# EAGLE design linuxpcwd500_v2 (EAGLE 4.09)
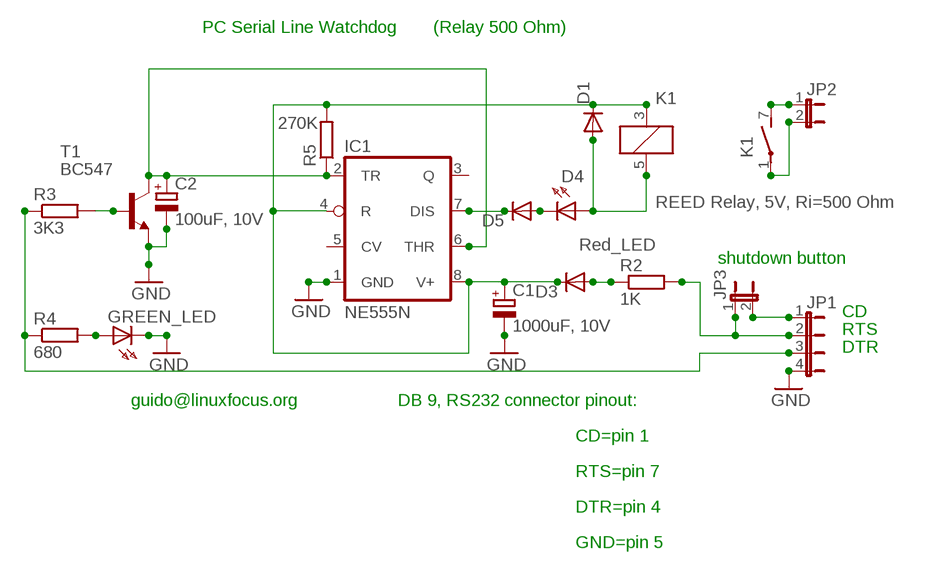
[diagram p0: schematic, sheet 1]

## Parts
C1  1000uF, 10V  CPOL-EUE3.5-10  [E3,5-10]
C2  100uF, 10V  CPOL-EUE3.5-10  [E3,5-10]
D1  DIODE-D-5  [D-5]
D3  DIODE-D-5  [D-5]
D4  Red_LED  LED3MM  [LED3MM]
D5  DIODE-D-5  [D-5]
GREEN_LED  LED3MM  [LED3MM]
IC1  NE555N  [DIL08]
JP1  JP4E  [JP4]
JP2  JP1E  [JP1]
JP3  JP1E  [JP1]
K1  REED Relay, 5V, Ri=500 Ohm  REED  [REED]
R2  1K  R-EU_0204/7  [0204/7]
R3  3K3  R-EU_0204/7  [0204/7]
R4  680  R-EU_0204/7  [0204/7]
R5  270K  R-EU_0204/7  [0204/7]
T1  BC547  [TO92]

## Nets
GND: C1.- C2.- GREEN_LED.K(C) IC1.1(GND) JP1.4 T1.1(E)
N$1: GREEN_LED.A R4.2
N$2: C2.+ IC1.2(TR) IC1.6(THR) R5.1 T1.3(C)
N$4: D4.K(C) D5.A
N$5: R3.2 T1.2(B)
N$6: D3.A R2.1
N$7: D5.C IC1.7(DIS)
N$8: JP2.1 K1.7(2:S)
N$9: D1.A D4.A K1.5(1:-)
N$10: JP2.2 K1.1(2:P)
N$13: JP1.1 JP3.2
N$14: JP1.2 JP3.1 R2.2
N$15: JP1.3 R3.1 R4.1
V+: C1.+ D1.C D3.C IC1.4(R) IC1.8(V+) K1.3(1:+) R5.2
Unconnected: IC1.3(Q) IC1.5(CV)

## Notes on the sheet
- PC Serial Line Watchdog | (Relay 500 Ohm)
- shutdown button
- CD
- RTS
- DTR
- guido@linuxfocus.org | DB 9, RS232 connector pinout:
- CD=pin 1
- RTS=pin 7
- DTR=pin 4
- GND=pin 5

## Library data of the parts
C1 C2 = rclgus:CPOL-EU: POLARIZED CAPACITOR, European symbol
D1 D3 D5 = diode:DIODE-: DIODE
D4 = led:LED3MM: LED
GREEN_LED = led:LED: LED
IC1 = linear:*555: TIMER
JP1 = jumper:JP4E: JUMPER
JP2 JP3 = jumper:JP1E: JUMPER
K1 = relay:REED: RELAY reed, 1 x norm. open with polarity, grid 5.08
R2 R3 R5 = rclgus:R-EU_: RESISTOR, European symbol
R4 = rcl:R-EU_: RESISTOR, European symbol
T1 = transistor-npn:BC547: NPN TRANSISTOR

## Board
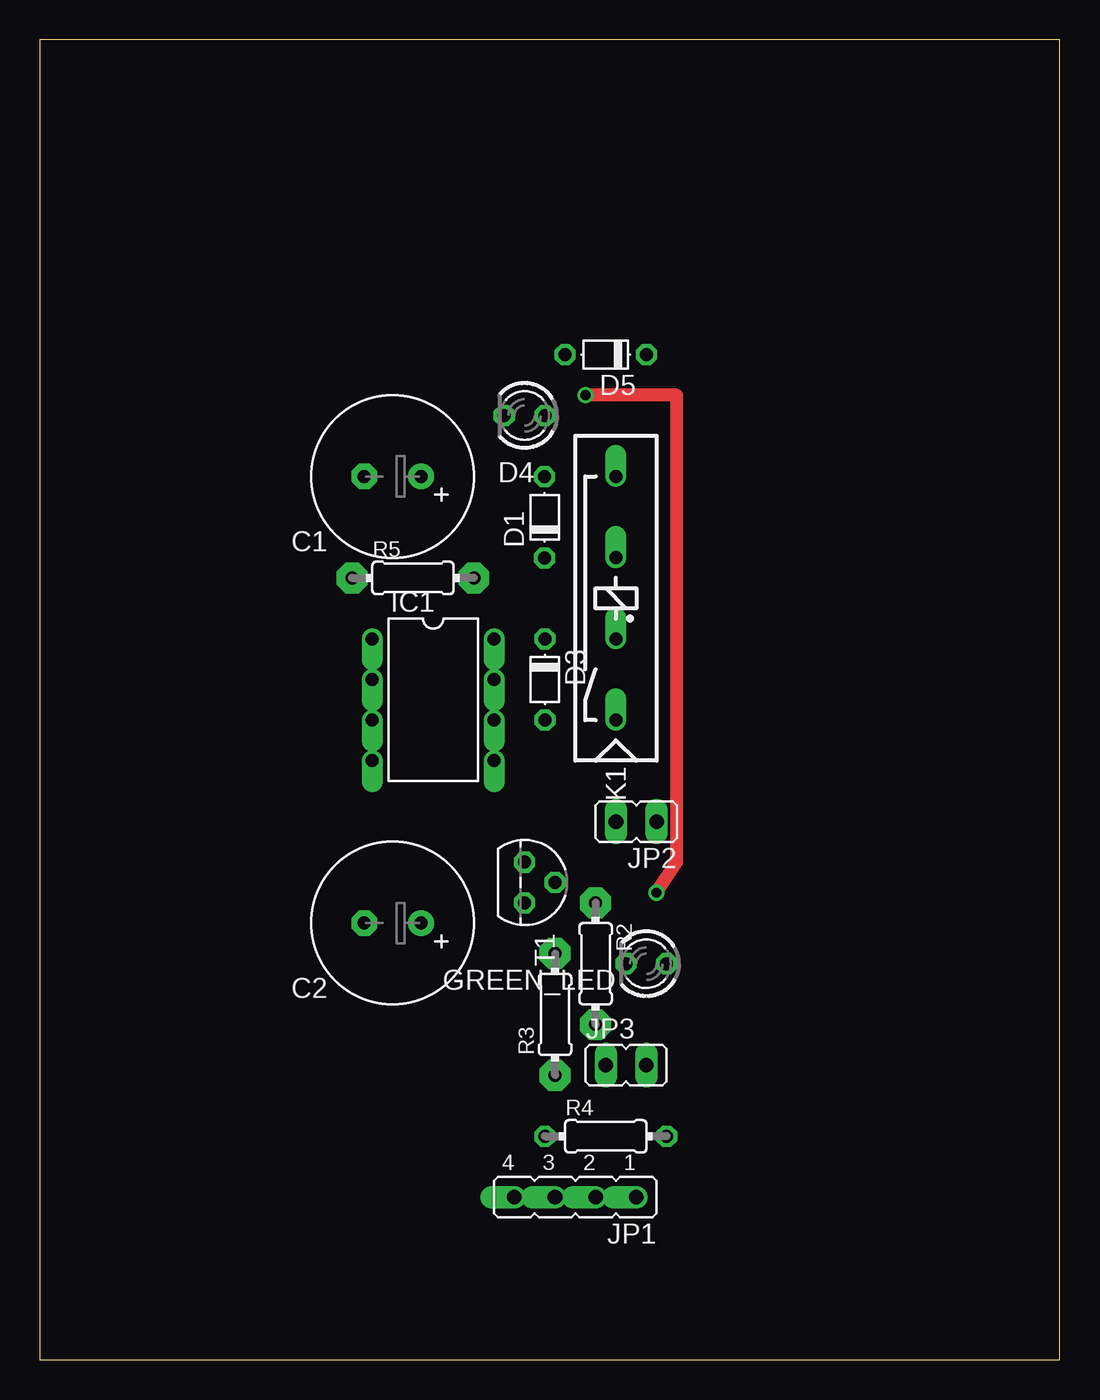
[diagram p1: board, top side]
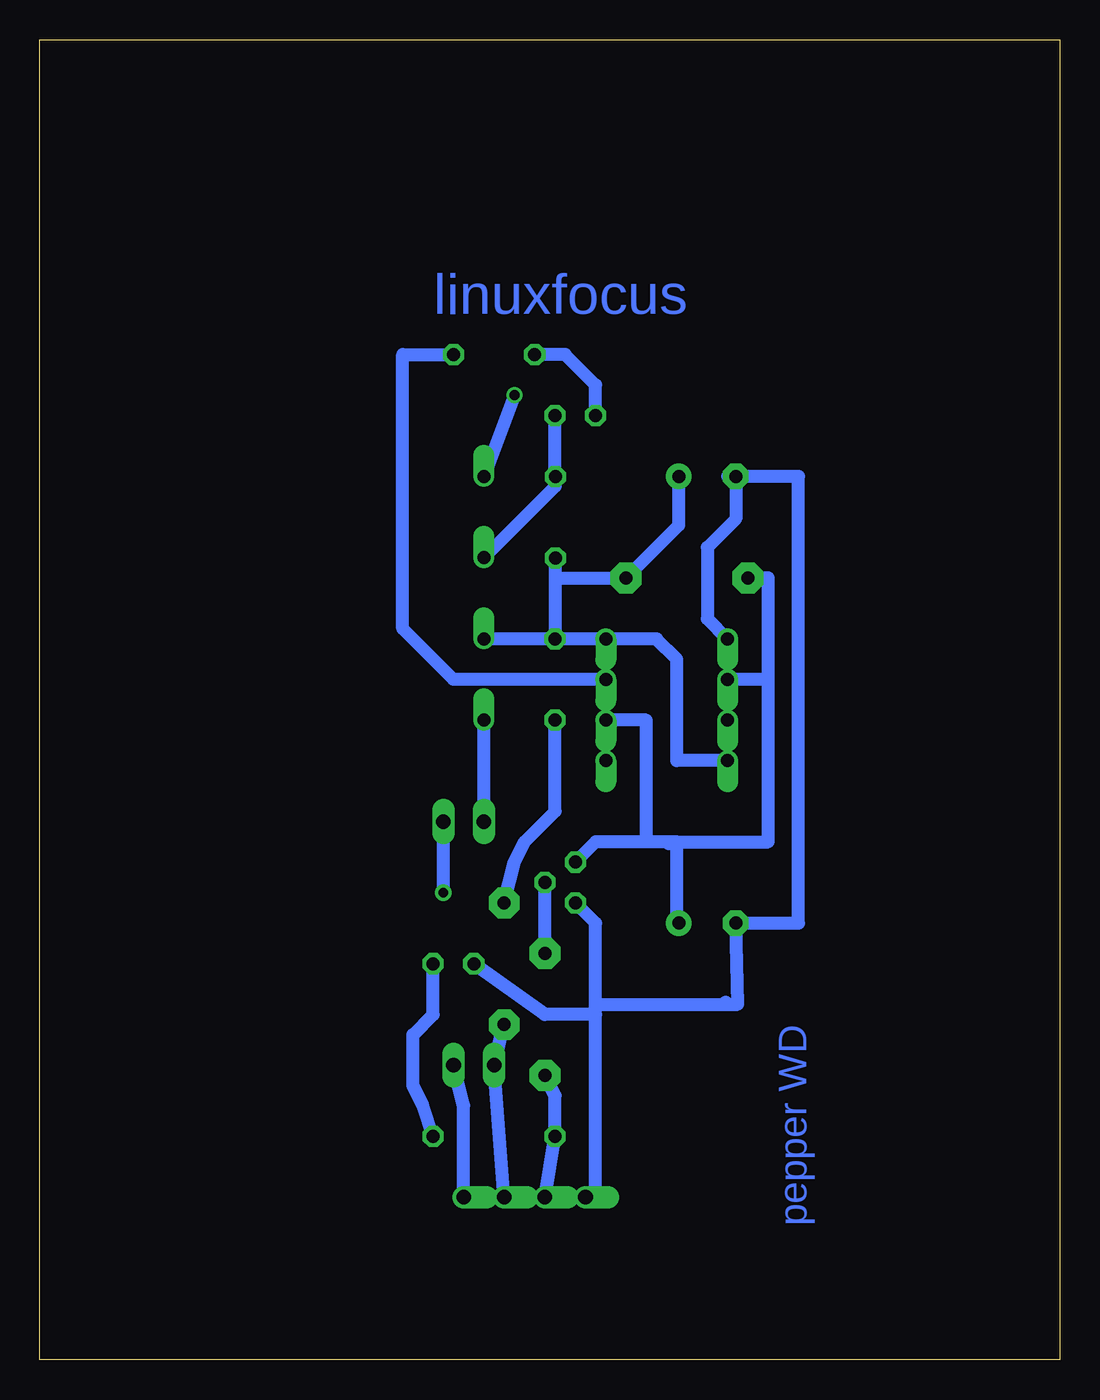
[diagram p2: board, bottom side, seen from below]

Size 63.8 x 82.54 mm. Coordinates in mm from the lower left corner, seen from the top.
Outline: 0,0 63.8,0 63.8,82.54 0,82.54 0,0
Copper layers used: Top, Bottom

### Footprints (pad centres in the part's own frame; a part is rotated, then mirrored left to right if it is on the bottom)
E3,5-10 = drill 0.813 pad 1.6 round: + -1.778,0 | drill 0.813 pad 1.6 octagon: - 1.778,0
D-5 = drill 0.813 octagon: A 2.54,0; C -2.54,0
LED3MM = drill 0.813 octagon: A -1.27,0; K 1.27,0
DIL08 = drill 0.813 offset: 1 -3.81,-3.81; 2 -1.27,-3.81; 3 1.27,-3.81; 4 3.81,-3.81; 5 3.81,3.81; 6 1.27,3.81; 7 -1.27,3.81; 8 -3.81,3.81
JP4 = drill 0.914 offset: 1 -3.81,0; 2 -1.27,0; 3 1.27,0; 4 3.81,0
JP1 = drill 0.914 long: 1 0,-1.27; 2 0,1.27
REED = drill 0.813 offset: 1 -17.78,2.54; 3 -12.7,2.54; 5 -7.62,2.54; 7 -2.54,2.54
0204/7 = drill 0.813 pad 1.93 octagon: 1 -3.81,0; 2 3.81,0
0204/7' = drill 0.813 octagon: 1 -3.81,0; 2 3.81,0
TO92 = drill 0.813 octagon: 1 1.27,0; 2 0,1.905; 3 -1.27,0

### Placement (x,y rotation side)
C1  22.06,55.24 180 top
C2  22.06,27.3 180 top
D1  31.57,52.68 90 top
D3  31.59,42.54 270 top
D4  30.32,59.05 180 top
D5  35.4,62.86 180 top
GREEN_LED  37.94,24.76 180 top
IC1  24.6,41.27 270 top
JP1  33.49,10.15 180 top
JP2  37.3,33.65 90 top
JP3  36.66,18.41 270 top
K1  38.57,57.78 90 top
R2  34.76,24.76 270 top
R3  32.22,21.59 90 top
R4  680  [0204/7']  35.4,13.96 0 top
R5  23.33,48.89 0 top
T1  30.32,29.84 270 top

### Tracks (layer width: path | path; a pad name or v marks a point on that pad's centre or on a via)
GND
  Bottom 0.813: IC1.1 22.06,46.35 22.06,50.8 20.28,52.57 C1.- | 20.79,22.22 20.92,22.35 | 29.05,22.22 20.79,22.22 | 29.05,22.22 29.05,27.3 T1.1 | C1.- 16.34,55.24 16.34,27.3 C2.- 20.16,22.22 20.79,22.22 | C1.- 20.79,55.24 | 29.05,21.59 29.05,22.22 | 29.05,21.59 29.05,10.15 JP1.4 | GREEN_LED.K 32.22,21.59 29.05,21.59
N$1
  Bottom 0.813: GREEN_LED.A 39.21,21.59 40.48,20.32 40.48,17.14 39.84,15.87 R4.2
N$2
  Bottom 0.813: IC1.6 25.87,40 25.87,32.38 | T1.3 29.05,32.38 25.87,32.38 | 23.97,32.38 18.25,32.38 18.25,42.54 | 23.97,32.38 24.6,32.38 | 24.6,32.38 24.47,32.25 23.97,32.38 | C2.+ 23.97,27.3 23.97,32.38 | 24.6,32.38 25.87,32.38 | R5.1 18.25,48.89 18.25,42.54 | 18.25,42.54 IC1.2
N$4
  Bottom 0.813: D5.A 30.95,62.86 29.05,60.96 D4.K
N$5
  Bottom 0.813: R3.2 T1.2
N$6
  Bottom 0.813: D3.A 31.59,34.29 33.49,32.38 34.12,31.11 R2.1
N$7
  Bottom 0.813: IC1.7 37.94,42.54 41.11,45.72 41.11,62.86 D5.C
N$8  (via drill 0.61)
  Top 0.813: v34.12,60.32 39.84,60.32 39.84,31.11 v38.57,29.2
  Bottom 0.813: v34.12,60.32 K1.7 | v38.57,29.2 JP2.1
N$9
  Bottom 0.813: D4.A 31.59,55.24 D1.A 31.57,54.62 K1.5
N$10
  Bottom 0.813: JP2.2 K1.1
N$13
  Bottom 0.813: JP3.2 37.3,15.87 JP1.1
N$14
  Bottom 0.813: R2.2 JP3.1 JP1.2
N$15
  Bottom 0.813: R3.1 31.59,16.5 R4.1 JP1.3
V+
  Bottom 0.61: IC1.8 29.05,45.08
  Bottom 0.813: IC1.4 23.97,37.46 23.97,43.81 25.23,45.08 IC1.8 D3.C | D3.C 31.57,45.1 D1.C 31.59,50.16 31.59,48.89 R5.2 23.84,52.19 C1.+ | D3.C K1.3

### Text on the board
Bottom: linuxfocus | pepper WD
